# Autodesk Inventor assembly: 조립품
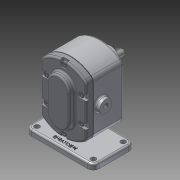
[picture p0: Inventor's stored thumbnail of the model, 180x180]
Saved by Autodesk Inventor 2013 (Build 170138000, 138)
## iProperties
Created: 2019-03
Part Number: 조립품
Document SubType Name: Assembly
Designer: Administrator
Author: Administrator
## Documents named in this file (11)
- C:\Users\Administrator\Desktop\490307v1019\조립품.iam
- C:\Users\Administrator\Desktop\490307v1019\본체.ipt
- C:\Users\Administrator\Desktop\490307v1019\메인축.ipt
- C:\Users\Administrator\Desktop\490307v1019\키 6 x 6 x 18.ipt
- C:\Users\Administrator\Desktop\490307v1019\스퍼기어.ipt
- C:\Users\Administrator\Desktop\490307v1019\베어링부시.ipt
- C:\Users\Administrator\Desktop\490307v1019\서브축.ipt
- C:\Users\Administrator\Desktop\490307v1019\개스킷.ipt
- C:\Users\Administrator\Desktop\490307v1019\커버.ipt
- C:\Users\Administrator\Desktop\490307v1019\볼트 M5.ipt
- C:\Users\Administrator\Desktop\490307v1019\오일 실 16 28 7.ipt
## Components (1 placed, 1 different names)
1. 개스킷:1
